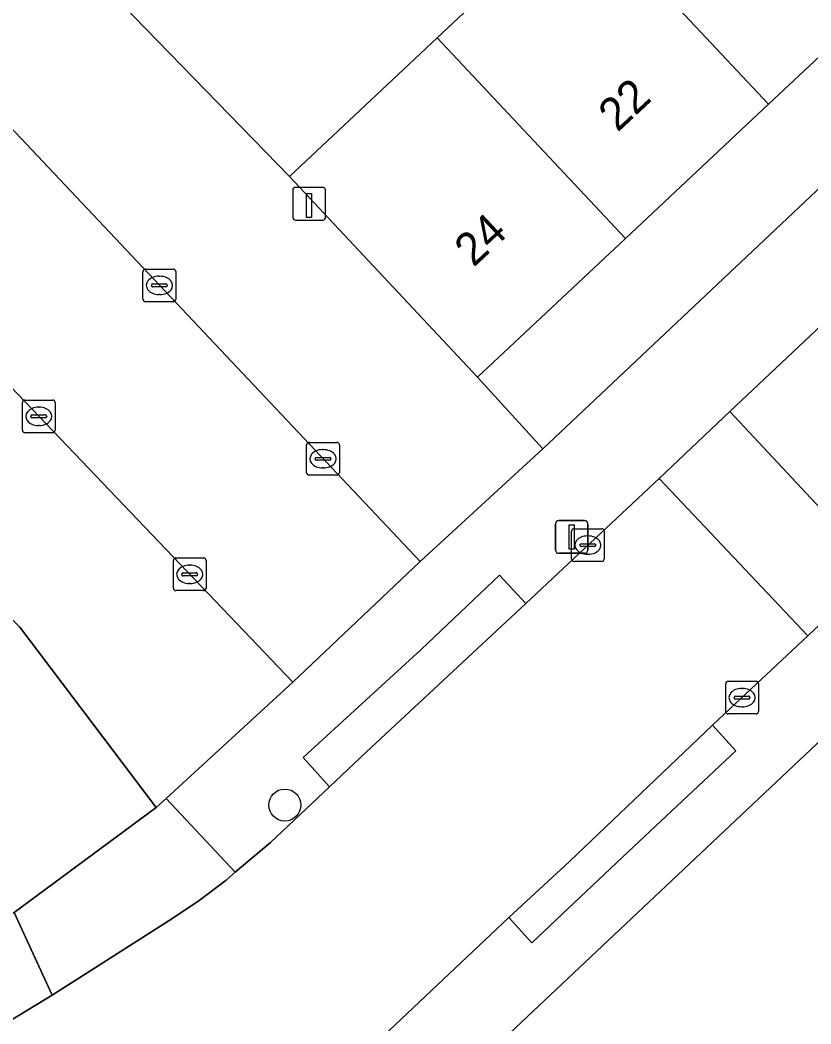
# Model space of a CAD drawing. Extents: x 159960 to 160866, y 382700 to 383354.
# Drawn here: x 160353.88 to 160378.08, y 383064.49 to 383095.2 of the extents above; entities that cross this region are included whole.
import ezdxf

# ---------------------------------------------------------------- set-up
doc = ezdxf.new("R2010")
doc.units = 0
for name, color, linetype in [('IMGEO_Boom', 7, 'Continuous'), ('IMGEO_Erf', 7, 'Continuous'), ('IMGEO_Kolk', 7, 'Continuous'), ('IMGEO_Laadpaal', 7, 'Continuous'), ('IMGEO_Lichtmast', 7, 'Continuous'), ('IMGEO_Pand', 7, 'Continuous'), ('IMGEO_Pand_nummerreeks', 7, 'Continuous'), ('IMGEO_Parkeervlak_open', 7, 'Continuous'), ('IMGEO_Rijbaan_lokaal_open', 7, 'Continuous'), ('IMGEO_Voetpad_open', 7, 'Continuous')]:
    doc.layers.add(name, color=color, linetype=linetype)

msp = doc.modelspace()

# ---------------------------------------------------------------- linework, layer by layer
at = {"layer": 'IMGEO_Boom'}
msp.add_circle((160361.978, 383071.184), 0.489, dxfattribs=at)
at = {"layer": 'IMGEO_Erf'}
for points in [[(160381.152, 383096.726), (160376.776, 383092.62), (160372.4, 383088.517), (160367.88, 383084.277), (160369.879, 383082.077), (160423.666, 383132.79)], [(160357.361, 383095.304), (160362.122, 383090.415), (160365.769, 383093.836), (160366.642, 383094.655), (160371.018, 383098.759)], [(160392.957, 383086.903), (160366.558, 383062.037)]]:
    msp.add_lwpolyline(points, dxfattribs=at)
at = {"layer": 'IMGEO_Kolk'}
for p, q in [((160357.639, 383086.655), (160357.639, 383087.507)), ((160357.714, 383087.581), (160358.566, 383087.581)), ((160358.64, 383087.507), (160358.64, 383086.655)), ((160357.898, 383087.075), (160357.898, 383087.087)), ((160357.941, 383087.124), (160358.339, 383087.124)), ((160358.127, 383087.361), (160358.152, 383087.361)), ((160358.382, 383087.087), (160358.382, 383087.075)), ((160358.336, 383087.038), (160357.938, 383087.038)), ((160358.15, 383086.801), (160358.125, 383086.801)), ((160358.566, 383086.581), (160357.714, 383086.581)), ((160353.949, 383082.648), (160353.949, 383083.5)), ((160354.024, 383083.574), (160354.876, 383083.574)), ((160354.95, 383083.5), (160354.95, 383082.648)), ((160354.251, 383083.117), (160354.649, 383083.117)), ((160354.437, 383083.354), (160354.462, 383083.354)), ((160354.208, 383083.068), (160354.208, 383083.08)), ((160354.646, 383083.031), (160354.248, 383083.031)), ((160354.46, 383082.794), (160354.435, 383082.794)), ((160354.692, 383083.08), (160354.692, 383083.068)), ((160354.876, 383082.574), (160354.024, 383082.574)), ((160362.647, 383081.35), (160362.647, 383082.202)), ((160362.722, 383082.276), (160363.574, 383082.276)), ((160363.648, 383082.202), (160363.648, 383081.35)), ((160363.135, 383082.056), (160363.16, 383082.056)), ((160362.906, 383081.77), (160362.906, 383081.782)), ((160363.344, 383081.733), (160362.946, 383081.733)), ((160362.949, 383081.819), (160363.347, 383081.819)), ((160363.39, 383081.782), (160363.39, 383081.77)), ((160363.574, 383081.276), (160362.722, 383081.276)), ((160363.158, 383081.496), (160363.133, 383081.496)), ((160370.751, 383078.709), (160370.751, 383079.561)), ((160370.826, 383079.635), (160371.678, 383079.635)), ((160371.239, 383079.415), (160371.264, 383079.415)), ((160371.752, 383079.561), (160371.752, 383078.709)), ((160371.01, 383079.129), (160371.01, 383079.141)), ((160371.053, 383079.178), (160371.451, 383079.178)), ((160371.494, 383079.141), (160371.494, 383079.129)), ((160371.448, 383079.092), (160371.05, 383079.092)), ((160371.262, 383078.855), (160371.237, 383078.855)), ((160358.569, 383077.816), (160358.569, 383078.668)), ((160358.644, 383078.742), (160359.496, 383078.742)), ((160359.057, 383078.522), (160359.082, 383078.522)), ((160359.57, 383078.668), (160359.57, 383077.816)), ((160371.678, 383078.635), (160370.826, 383078.635)), ((160358.828, 383078.236), (160358.828, 383078.248)), ((160359.266, 383078.199), (160358.868, 383078.199)), ((160358.871, 383078.285), (160359.269, 383078.285)), ((160359.312, 383078.248), (160359.312, 383078.236)), ((160359.08, 383077.962), (160359.055, 383077.962)), ((160359.496, 383077.742), (160358.644, 383077.742)), ((160375.471, 383074.044), (160375.471, 383074.896)), ((160375.546, 383074.97), (160376.398, 383074.97)), ((160376.472, 383074.896), (160376.472, 383074.044)), ((160375.773, 383074.513), (160376.171, 383074.513)), ((160375.959, 383074.75), (160375.984, 383074.75)), ((160375.73, 383074.464), (160375.73, 383074.476)), ((160376.168, 383074.427), (160375.77, 383074.427)), ((160375.982, 383074.19), (160375.957, 383074.19)), ((160376.214, 383074.476), (160376.214, 383074.464)), ((160376.398, 383073.97), (160375.546, 383073.97))]:
    msp.add_line(p, q, dxfattribs=at)
for points in [[(160357.639, 383086.655), (160357.639, 383087.507)], [(160357.714, 383087.581), (160358.566, 383087.581)], [(160358.64, 383087.507), (160358.64, 383086.655)], [(160358.566, 383086.581), (160357.714, 383086.581)], [(160353.949, 383082.648), (160353.949, 383083.5)], [(160354.024, 383083.574), (160354.876, 383083.574)], [(160354.95, 383083.5), (160354.95, 383082.648)], [(160354.876, 383082.574), (160354.024, 383082.574)], [(160362.647, 383081.35), (160362.647, 383082.202)], [(160362.722, 383082.276), (160363.574, 383082.276)], [(160363.648, 383082.202), (160363.648, 383081.35)], [(160363.574, 383081.276), (160362.722, 383081.276)], [(160370.751, 383078.709), (160370.751, 383079.561)], [(160370.826, 383079.635), (160371.678, 383079.635)], [(160371.752, 383079.561), (160371.752, 383078.709)], [(160358.569, 383077.816), (160358.569, 383078.668)], [(160358.644, 383078.742), (160359.496, 383078.742)], [(160359.57, 383078.668), (160359.57, 383077.816)], [(160371.678, 383078.635), (160370.826, 383078.635)], [(160359.496, 383077.742), (160358.644, 383077.742)], [(160375.471, 383074.044), (160375.471, 383074.896)], [(160375.546, 383074.97), (160376.398, 383074.97)], [(160376.472, 383074.896), (160376.472, 383074.044)], [(160376.398, 383073.97), (160375.546, 383073.97)]]:
    msp.add_lwpolyline(points, dxfattribs=at)
for centre, radius, start, end in [((160357.716, 383087.505), 0.0765, 91.552, 178.448), ((160357.716, 383087.505), 0.0765, 91.552, 178.448), ((160358.564, 383087.505), 0.0765, 1.552, 88.448), ((160358.564, 383087.505), 0.0765, 1.552, 88.448), ((160357.938, 383087.084), 0.0403, 85.8775, 175.7526), ((160358.343, 383087.086), 0.0386, 1.7309, 96.639), ((160357.935, 383087.074), 0.0366, 178.938, 274.7102), ((160358.339, 383087.081), 0.043, 264.8664, 352.4533), ((160357.716, 383086.657), 0.0765, 181.552, 268.448), ((160357.716, 383086.657), 0.0765, 181.552, 268.448), ((160358.564, 383086.657), 0.0765, 271.552, 358.448), ((160358.564, 383086.657), 0.0765, 271.552, 358.448), ((160354.026, 383083.498), 0.0765, 91.552, 178.448), ((160354.026, 383083.498), 0.0765, 91.552, 178.448), ((160354.874, 383083.498), 0.0765, 1.552, 88.448), ((160354.874, 383083.498), 0.0765, 1.552, 88.448), ((160354.248, 383083.077), 0.0403, 85.8775, 175.7526), ((160354.653, 383083.079), 0.0386, 1.7309, 96.639), ((160354.245, 383083.067), 0.0366, 178.938, 274.7102), ((160354.649, 383083.074), 0.043, 264.8664, 352.4533), ((160354.026, 383082.65), 0.0765, 181.552, 268.448), ((160354.026, 383082.65), 0.0765, 181.552, 268.448), ((160354.874, 383082.65), 0.0765, 271.552, 358.448), ((160354.874, 383082.65), 0.0765, 271.552, 358.448), ((160362.724, 383082.2), 0.0765, 91.552, 178.448), ((160362.724, 383082.2), 0.0765, 91.552, 178.448), ((160363.572, 383082.2), 0.0765, 1.552, 88.448), ((160363.572, 383082.2), 0.0765, 1.552, 88.448), ((160362.946, 383081.779), 0.0403, 85.8775, 175.7526), ((160362.943, 383081.769), 0.0366, 178.938, 274.7102), ((160363.347, 383081.776), 0.043, 264.8664, 352.4533), ((160363.351, 383081.781), 0.0386, 1.7309, 96.639), ((160362.724, 383081.352), 0.0765, 181.552, 268.448), ((160362.724, 383081.352), 0.0765, 181.552, 268.448), ((160363.572, 383081.352), 0.0765, 271.552, 358.448), ((160363.572, 383081.352), 0.0765, 271.552, 358.448), ((160370.828, 383079.559), 0.0765, 91.552, 178.448), ((160370.828, 383079.559), 0.0765, 91.552, 178.448), ((160371.676, 383079.559), 0.0765, 1.552, 88.448), ((160371.676, 383079.559), 0.0765, 1.552, 88.448), ((160371.05, 383079.138), 0.0403, 85.8775, 175.7526), ((160371.047, 383079.128), 0.0366, 178.938, 274.7102), ((160371.451, 383079.135), 0.043, 264.8664, 352.4533), ((160371.455, 383079.14), 0.0386, 1.7309, 96.639), ((160358.646, 383078.666), 0.0765, 91.552, 178.448), ((160358.646, 383078.666), 0.0765, 91.552, 178.448), ((160359.494, 383078.666), 0.0765, 1.552, 88.448), ((160359.494, 383078.666), 0.0765, 1.552, 88.448), ((160370.828, 383078.711), 0.0765, 181.552, 268.448), ((160370.828, 383078.711), 0.0765, 181.552, 268.448), ((160371.676, 383078.711), 0.0765, 271.552, 358.448), ((160371.676, 383078.711), 0.0765, 271.552, 358.448), ((160358.868, 383078.245), 0.0403, 85.8775, 175.7526), ((160358.865, 383078.235), 0.0366, 178.938, 274.7102), ((160359.269, 383078.242), 0.043, 264.8664, 352.4533), ((160359.273, 383078.247), 0.0386, 1.7309, 96.639), ((160358.646, 383077.818), 0.0765, 181.552, 268.448), ((160358.646, 383077.818), 0.0765, 181.552, 268.448), ((160359.494, 383077.818), 0.0765, 271.552, 358.448), ((160359.494, 383077.818), 0.0765, 271.552, 358.448), ((160375.548, 383074.894), 0.0765, 91.552, 178.448), ((160375.548, 383074.894), 0.0765, 91.552, 178.448), ((160376.396, 383074.894), 0.0765, 1.552, 88.448), ((160376.396, 383074.894), 0.0765, 1.552, 88.448), ((160375.77, 383074.473), 0.0403, 85.8775, 175.7526), ((160376.175, 383074.475), 0.0386, 1.7309, 96.639), ((160375.767, 383074.463), 0.0366, 178.938, 274.7102), ((160376.171, 383074.47), 0.043, 264.8664, 352.4533), ((160375.548, 383074.046), 0.0765, 181.552, 268.448), ((160375.548, 383074.046), 0.0765, 181.552, 268.448), ((160376.396, 383074.046), 0.0765, 271.552, 358.448), ((160376.396, 383074.046), 0.0765, 271.552, 358.448)]:
    msp.add_arc(centre, radius, start, end, dxfattribs=at)
for centre, major_axis, ratio, start_param, end_param in [((160358.126, 383087.081), (-0.387, 0.002), 0.722429, 4.712389, 7.853982), ((160358.151, 383087.081), (-0.39, 0.002), 0.717154, 1.570796, 4.712389), ((160354.436, 383083.074), (-0.387, 0.002), 0.722429, 4.712389, 7.853982), ((160354.461, 383083.074), (-0.39, 0.002), 0.717154, 1.570796, 4.712389), ((160363.134, 383081.776), (-0.387, 0.002), 0.722429, 4.712389, 7.853982), ((160363.159, 383081.776), (-0.39, 0.002), 0.717154, 1.570796, 4.712389), ((160371.238, 383079.135), (-0.387, 0.002), 0.722429, 4.712389, 7.853982), ((160371.263, 383079.135), (-0.39, 0.002), 0.717154, 1.570796, 4.712389), ((160359.056, 383078.242), (-0.387, 0.002), 0.722429, 4.712389, 7.853982), ((160359.081, 383078.242), (-0.39, 0.002), 0.717154, 1.570796, 4.712389), ((160375.958, 383074.47), (-0.387, 0.002), 0.722429, 4.712389, 7.853982), ((160375.983, 383074.47), (-0.39, 0.002), 0.717154, 1.570796, 4.712389)]:
    msp.add_ellipse(centre, major_axis=major_axis, ratio=ratio, start_param=start_param, end_param=end_param, dxfattribs=at)
at = {"layer": 'IMGEO_Laadpaal'}
for p, q in [((160362.224, 383089.996), (160362.224, 383089.155)), ((160362.224, 383089.996), (160362.224, 383089.155)), ((160363.14, 383090.08), (160362.299, 383090.08)), ((160363.14, 383090.08), (160362.299, 383090.08)), ((160363.224, 383089.164), (160363.224, 383090.005)), ((160363.224, 383089.164), (160363.224, 383090.005)), ((160362.308, 383089.08), (160363.149, 383089.08)), ((160362.308, 383089.08), (160363.149, 383089.08))]:
    msp.add_line(p, q, dxfattribs=at)
msp.add_lwpolyline([(160362.639, 383089.893), (160362.799, 383089.893), (160362.799, 383089.16), (160362.639, 383089.16), (160362.639, 383089.893)], dxfattribs=at)
for centre, start, end in [((160362.302, 383090.002), 92.4484, 184.2845), ((160362.302, 383090.002), 92.4484, 184.2845), ((160363.146, 383090.002), 2.4484, 94.2845), ((160363.146, 383090.002), 2.4484, 94.2845), ((160362.302, 383089.158), 182.4484, 274.2845), ((160362.302, 383089.158), 182.4484, 274.2845), ((160363.146, 383089.158), 272.4484, 4.2845), ((160363.146, 383089.158), 272.4484, 4.2845)]:
    msp.add_arc(centre, 0.0779, start, end, dxfattribs=at)
at = {"layer": 'IMGEO_Lichtmast'}
for p, q in [((160370.264, 383078.984), (160370.264, 383079.784)), ((160370.264, 383079.784), (160370.264, 383078.984)), ((160370.364, 383079.884), (160371.154, 383079.884)), ((160371.154, 383079.884), (160370.364, 383079.884)), ((160371.254, 383079.784), (160371.254, 383078.984)), ((160371.254, 383078.984), (160371.254, 383079.784)), ((160371.154, 383078.884), (160370.364, 383078.884)), ((160370.364, 383078.884), (160371.154, 383078.884))]:
    msp.add_line(p, q, dxfattribs=at)
msp.add_lwpolyline([(160370.684, 383079.759), (160370.834, 383079.759), (160370.834, 383079.009), (160370.684, 383079.009), (160370.684, 383079.759)], dxfattribs=at)
for centre, start, end in [((160370.364, 383079.784), 90, 180), ((160370.364, 383079.784), 90, 180), ((160371.154, 383079.784), 0, 90), ((160371.154, 383079.784), 360, 90), ((160370.364, 383078.984), 180, 270), ((160370.364, 383078.984), 180, 270), ((160371.154, 383078.984), 270, 0), ((160371.154, 383078.984), 270, 0)]:
    msp.add_arc(centre, 0.1, start, end, dxfattribs=at)
at = {"layer": 'IMGEO_Pand'}
for points in [[(160376.776, 383092.62), (160381.152, 383096.726), (160373.311, 383105.084), (160368.935, 383100.98), (160371.018, 383098.759)], [(160376.776, 383092.62), (160371.018, 383098.759), (160366.642, 383094.655), (160372.4, 383088.517)], [(160366.642, 383094.655), (160365.769, 383093.836), (160362.122, 383090.415), (160367.88, 383084.277), (160372.4, 383088.517)]]:
    msp.add_lwpolyline(points, close=True, dxfattribs=at)
at = {"layer": 'IMGEO_Parkeervlak_open'}
for points in [[(160367.88, 383084.277), (160362.122, 383090.415), (160357.361, 383095.304), (160355.062, 383097.754), (160351.35, 383094.272), (160366.117, 383078.629), (160369.879, 383082.077)], [(160347.343, 383090.51), (160344.072, 383087.441), (160343.659, 383087.021), (160353.872, 383076.62), (160358.04, 383071.104), (160358.346, 383071.384), (160362.229, 383074.94)]]:
    msp.add_lwpolyline(points, close=True, dxfattribs=at)
at = {"layer": 'IMGEO_Rijbaan_lokaal_open'}
for points in [[(160403.552, 383100.436), (160405.554, 383102.316), (160415.821, 383111.942), (160411.292, 383116.793), (160405.8, 383111.613), (160397.4, 383103.731), (160393.269, 383099.855), (160387.865, 383094.781), (160375.599, 383083.221), (160380.124, 383078.379), (160390.773, 383088.421), (160397.489, 383094.742), (160399.709, 383096.829)], [(160351.35, 383094.272), (160347.343, 383090.51), (160362.229, 383074.94), (160366.117, 383078.629)], [(160375.599, 383083.221), (160373.431, 383081.176), (160377.981, 383076.364), (160380.124, 383078.379)]]:
    msp.add_lwpolyline(points, close=True, dxfattribs=at)
for points in [[(160353.698, 383067.892), (160358.04, 383071.104), (160353.872, 383076.62), (160343.659, 383087.021), (160333.639, 383097.319), (160331.452, 383095.137), (160329.265, 383092.956), (160327.078, 383090.774), (160324.891, 383088.593), (160322.704, 383086.411), (160320.517, 383084.23), (160318.33, 383082.048), (160316.143, 383079.867), (160313.956, 383077.685), (160311.769, 383075.504), (160309.582, 383073.322), (160307.395, 383071.141), (160305.208, 383068.959), (160303.025, 383066.781), (160300.321, 383064.084), (160315.353, 383049.161), (160318.121, 383046.413), (160325.142, 383050.537), (160324.477, 383051.186)], [(160363.348, 383062.566), (160368.837, 383067.739), (160370.702, 383069.471), (160375.064, 383073.623), (160375.61, 383074.142), (160377.981, 383076.364), (160373.431, 383081.176), (160369.356, 383077.35), (160368.91, 383076.931), (160364.471, 383072.803), (160363.349, 383071.742), (160361.545, 383070.036), (160360.462, 383069.126), (160360.181, 383068.89), (160359.359, 383068.261), (160358.518, 383067.704), (160354.861, 383065.364), (160349.595, 383062.176)]]:
    msp.add_lwpolyline(points, dxfattribs=at)
at = {"layer": 'IMGEO_Voetpad_open'}
for points in [[(160434.718, 383143.083), (160432.132, 383140.666), (160427.441, 383136.302), (160423.666, 383132.79), (160369.879, 383082.077), (160366.117, 383078.629), (160362.229, 383074.94), (160358.346, 383071.384), (160360.462, 383069.126), (160361.545, 383070.036), (160363.349, 383071.742), (160362.543, 383072.636), (160366.151, 383075.937), (160368.547, 383078.218), (160369.356, 383077.35), (160373.431, 383081.176), (160375.599, 383083.221), (160387.865, 383094.781), (160393.269, 383099.855), (160397.4, 383103.731), (160405.8, 383111.613), (160411.292, 383116.793)], [(160392.957, 383086.903), (160392.983, 383086.934), (160400.001, 383093.994), (160399.824, 383094.214), (160402.15, 383096.388), (160402.323, 383096.17), (160405.806, 383099.371), (160403.865, 383100.106), (160400.544, 383096.98), (160397.808, 383094.397), (160397.489, 383094.742), (160390.773, 383088.421), (160380.124, 383078.379), (160377.981, 383076.364), (160375.61, 383074.142), (160375.064, 383073.623), (160375.779, 383072.837), (160372.493, 383069.76), (160369.542, 383066.97), (160368.837, 383067.739), (160363.348, 383062.566), (160362.612, 383061.814)], [(160366.558, 383062.037), (160392.957, 383086.903)]]:
    msp.add_lwpolyline(points, dxfattribs=at)
for points in [[(160369.356, 383077.35), (160368.547, 383078.218), (160366.151, 383075.937), (160362.543, 383072.636), (160363.349, 383071.742), (160364.471, 383072.803), (160368.91, 383076.931)], [(160375.064, 383073.623), (160370.702, 383069.471), (160368.837, 383067.739), (160369.542, 383066.97), (160372.493, 383069.76), (160375.779, 383072.837)], [(160360.462, 383069.126), (160358.346, 383071.384), (160358.04, 383071.104), (160353.698, 383067.892), (160354.861, 383065.364), (160358.518, 383067.704), (160359.359, 383068.261), (160360.181, 383068.89)], [(160344.875, 383059.245), (160349.595, 383062.176), (160354.861, 383065.364), (160353.698, 383067.892), (160336.135, 383057.218), (160325.761, 383050.913), (160327.187, 383048.566), (160337.499, 383054.792)]]:
    msp.add_lwpolyline(points, close=True, dxfattribs=at)

# ---------------------------------------------------------------- texts
at = {"layer": 'IMGEO_Pand_nummerreeks'}
for s, p in [('22', (160372.16, 383091.746)), ('24', (160367.756, 383087.616))]:
    msp.add_text(s, height=1, rotation=43.1654, dxfattribs=at).set_placement(p)

doc.saveas('drawing.dxf')
